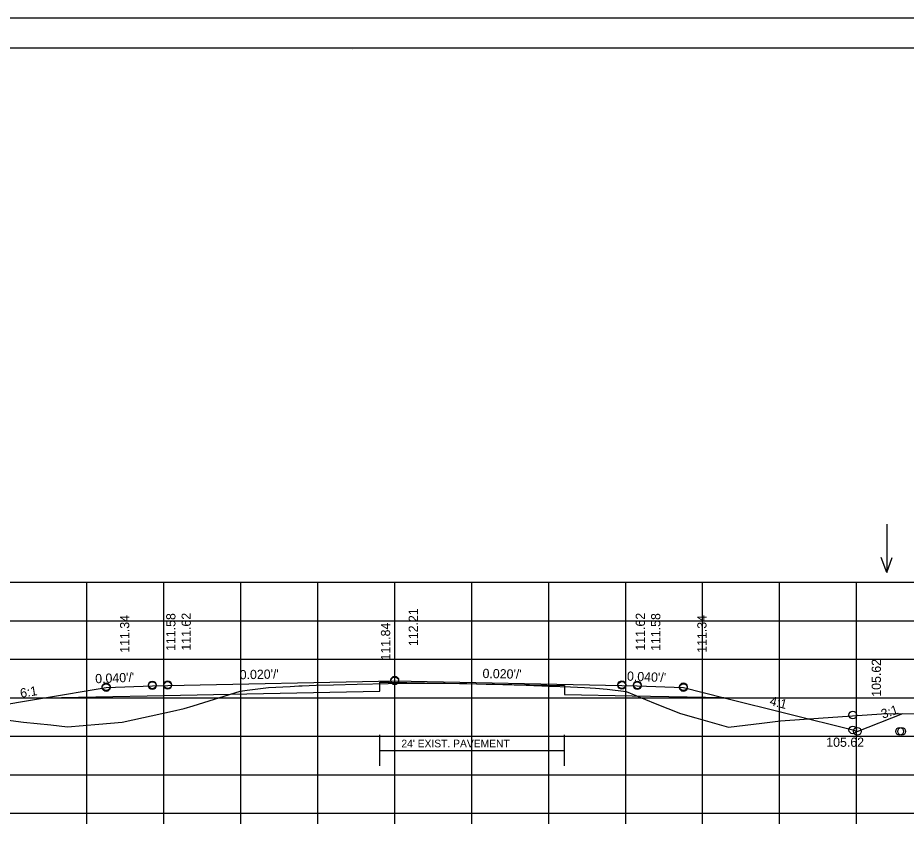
# Model space of a CAD drawing. Extents: x 1175611 to 1176402, y -433344 to -416213.
# Drawn here: x 1175732 to 1175847.4, y -424702.1 to -424596.7 of the extents above; entities that cross this region are included whole.
import ezdxf

# ---------------------------------------------------------------- set-up
doc = ezdxf.new("R2010")
doc.units = 0
for name, color, linetype in [('R_Alt Surface', 7, 'Continuous'), ('R_Axis', 7, 'Continuous'), ('R_Border', 7, 'Continuous'), ('R_Exist Surface', 7, 'Continuous'), ('R_Fin Surface', 7, 'Continuous'), ('R_Grid', 7, 'Continuous'), ('R_No Plot', 7, 'Continuous'), ('R_Water Annot', 7, 'Continuous'), ('R_Xsect Elev', 7, 'Continuous'), ('R_Xsect Slope', 7, 'Continuous')]:
    doc.layers.add(name, color=color, linetype=linetype)

msp = doc.modelspace()

# ---------------------------------------------------------------- linework, layer by layer
at = {"layer": 'R_Alt Surface'}
msp.add_line((1175779.02, -424691.87), (1175803.02, -424691.87), dxfattribs=at)
for points in [[(1175735.42, -424685.05), (1175748.79, -424684.78), (1175779.02, -424684.18), (1175779.02, -424683.01), (1175780.29, -424682.99), (1175803.02, -424683.44), (1175803.02, -424684.61), (1175811.79, -424684.78), (1175823.72, -424685.02)], [(1175779.02, -424693.87), (1175779.02, -424689.87)], [(1175803.02, -424693.87), (1175803.02, -424689.87)]]:
    msp.add_lwpolyline(points, dxfattribs=at)
at = {"layer": 'R_Axis'}
for p, q in [((1175640.97, -424700.03), (1175920.97, -424700.03)), ((1175740.97, -424701.43), (1175740.97, -424700.03)), ((1175750.97, -424701.43), (1175750.97, -424700.03)), ((1175760.97, -424701.43), (1175760.97, -424700.03)), ((1175770.97, -424701.43), (1175770.97, -424700.03)), ((1175780.97, -424701.43), (1175780.97, -424700.03)), ((1175790.97, -424701.43), (1175790.97, -424700.03)), ((1175800.97, -424701.43), (1175800.97, -424700.03)), ((1175810.97, -424701.43), (1175810.97, -424700.03)), ((1175820.97, -424701.43), (1175820.97, -424700.03)), ((1175830.97, -424701.43), (1175830.97, -424700.03)), ((1175840.97, -424701.43), (1175840.97, -424700.03))]:
    msp.add_line(p, q, dxfattribs=at)
at = {"layer": 'R_Border'}
for p, q in [((1175622.97, -424600.57), (1175939.15, -424600.57)), ((1175775.49, -424600.83), (1175775.49, -424600.83)), ((1175775.49, -424600.83), (1175775.49, -424600.83))]:
    msp.add_line(p, q, dxfattribs=at)
at = {"layer": 'R_Exist Surface'}
msp.add_lwpolyline([(1175727.73, -424687.54), (1175732.71, -424688.21), (1175736.27, -424688.56), (1175738.44, -424688.83), (1175742.52, -424688.46), (1175745.57, -424688.21), (1175752.07, -424686.79), (1175753.61, -424686.44), (1175754.77, -424686.08), (1175760.87, -424684.18), (1175761.79, -424684.07), (1175764.54, -424683.71), (1175767.36, -424683.56), (1175768.51, -424683.49), (1175768.65, -424683.48), (1175768.93, -424683.47), (1175770.76, -424683.42), (1175773.02, -424683.35), (1175776.09, -424683.27), (1175780.11, -424683.17), (1175780.79, -424683.15), (1175781.62, -424683.13), (1175784.89, -424683.13), (1175787.51, -424683.14), (1175790.33, -424683.2), (1175792.85, -424683.26), (1175795, -424683.33), (1175796.48, -424683.36), (1175798.06, -424683.41), (1175801.09, -424683.52), (1175803.79, -424683.63), (1175805.63, -424683.71), (1175806.34, -424683.74), (1175807.05, -424683.78), (1175808.58, -424683.94), (1175811.02, -424684.22), (1175814.82, -424685.79), (1175818.08, -424687.1), (1175820.08, -424687.66), (1175824.32, -424688.87), (1175828.65, -424688.35), (1175831.07, -424688.03), (1175836.62, -424687.65), (1175844.85, -424687.07), (1175884.29, -424687.26)], dxfattribs=at)
at = {"layer": 'R_Fin Surface'}
msp.add_lwpolyline([(1175709, -424687.19), (1175715.52, -424689.36), (1175721.47, -424687.38), (1175735.2, -424685.09), (1175743.47, -424683.71), (1175749.47, -424683.47), (1175751.47, -424683.43), (1175780.97, -424682.84), (1175810.47, -424683.43), (1175812.47, -424683.47), (1175818.47, -424683.71), (1175823.75, -424685.03), (1175840.47, -424689.21), (1175841.06, -424689.4), (1175846.97, -424687.08)], dxfattribs=at)
at = {"layer": 'R_Grid'}
for p, q in [((1175640.97, -424670.03), (1175920.97, -424670.03)), ((1175740.97, -424700.03), (1175740.97, -424670.03)), ((1175750.97, -424700.03), (1175750.97, -424670.03)), ((1175760.97, -424700.03), (1175760.97, -424670.03)), ((1175770.97, -424700.03), (1175770.97, -424670.03)), ((1175780.97, -424700.03), (1175780.97, -424670.03)), ((1175790.97, -424700.03), (1175790.97, -424670.03)), ((1175800.97, -424700.03), (1175800.97, -424670.03)), ((1175810.97, -424700.03), (1175810.97, -424670.03)), ((1175820.97, -424700.03), (1175820.97, -424670.03)), ((1175830.97, -424700.03), (1175830.97, -424670.03)), ((1175840.97, -424700.03), (1175840.97, -424670.03)), ((1175640.97, -424675.03), (1175920.97, -424675.03)), ((1175640.97, -424680.03), (1175920.97, -424680.03)), ((1175640.97, -424685.03), (1175920.97, -424685.03)), ((1175640.97, -424690.03), (1175920.97, -424690.03)), ((1175640.97, -424695.03), (1175920.97, -424695.03)), ((1175640.97, -424700.03), (1175920.97, -424700.03))]:
    msp.add_line(p, q, dxfattribs=at)
at = {"layer": 'R_No Plot'}
msp.add_line((1175610.57, -424596.68), (1175943.91, -424596.68), dxfattribs=at)
msp.add_lwpolyline([(1175610.57, -424596.68), (1175943.91, -424596.68), (1175943.91, -424810.01), (1175610.57, -424810.01)], close=True, dxfattribs=at)
for centre in [(1175749.47, -424683.37), (1175749.47, -424683.47), (1175751.47, -424683.33), (1175751.47, -424683.43), (1175780.97, -424682.74), (1175780.97, -424682.84), (1175810.47, -424683.33), (1175810.47, -424683.43), (1175812.47, -424683.37), (1175812.47, -424683.47), (1175743.47, -424683.61), (1175743.47, -424683.71), (1175818.47, -424683.61), (1175818.47, -424683.71), (1175840.47, -424687.28), (1175840.47, -424689.21), (1175841.06, -424689.4), (1175846.56, -424689.4), (1175846.83, -424689.4)]:
    msp.add_circle(centre, 0.5, dxfattribs=at)
at = {"layer": 'R_Water Annot'}
for p, q in [((1175844.88, -424662.47), (1175844.88, -424668.75)), ((1175844.88, -424668.75), (1175844.18, -424666.83)), ((1175844.88, -424668.75), (1175845.58, -424666.83))]:
    msp.add_line(p, q, dxfattribs=at)

# ---------------------------------------------------------------- texts
at = {"layer": 'R_Alt Surface'}
msp.add_text("24' EXIST. PAVEMENT", height=1, dxfattribs=at).set_placement((1175781.83, -424691.48))
at = {"layer": 'R_Xsect Elev'}
for s, p in [('112.21', (1175783.97, -424678.32)), ('111.34', (1175746.47, -424679.19)), ('111.58', (1175752.47, -424678.95)), ('111.62', (1175754.47, -424678.91)), ('111.62', (1175813.47, -424678.91)), ('111.58', (1175815.47, -424678.95)), ('111.34', (1175821.47, -424679.19)), ('111.84', (1175780.37, -424680.19)), ('105.62', (1175844.13, -424684.9))]:
    msp.add_text(s, height=1.2, rotation=90, dxfattribs=at).set_placement(p)
msp.add_text('105.62', height=1.2, dxfattribs=at).set_placement((1175837.03, -424691.41))
at = {"layer": 'R_Xsect Slope'}
for s, rotation, p in [("0.040'/'", 2.2906, (1175742.07, -424683.16)), ("0.020'/'", 1.1458, (1175760.83, -424682.64)), ("0.020'/'", 358.8542, (1175792.36, -424682.47)), ("0.040'/'", 357.7094, (1175811.12, -424682.81)), ('6:1', 9.4623, (1175732.39, -424685.05)), ('4:1', 345.9638, (1175829.59, -424685.97)), ('3:1', 18.4349, (1175844.38, -424687.77))]:
    msp.add_text(s, height=1.2, rotation=rotation, dxfattribs=at).set_placement(p)

doc.saveas('drawing.dxf')
